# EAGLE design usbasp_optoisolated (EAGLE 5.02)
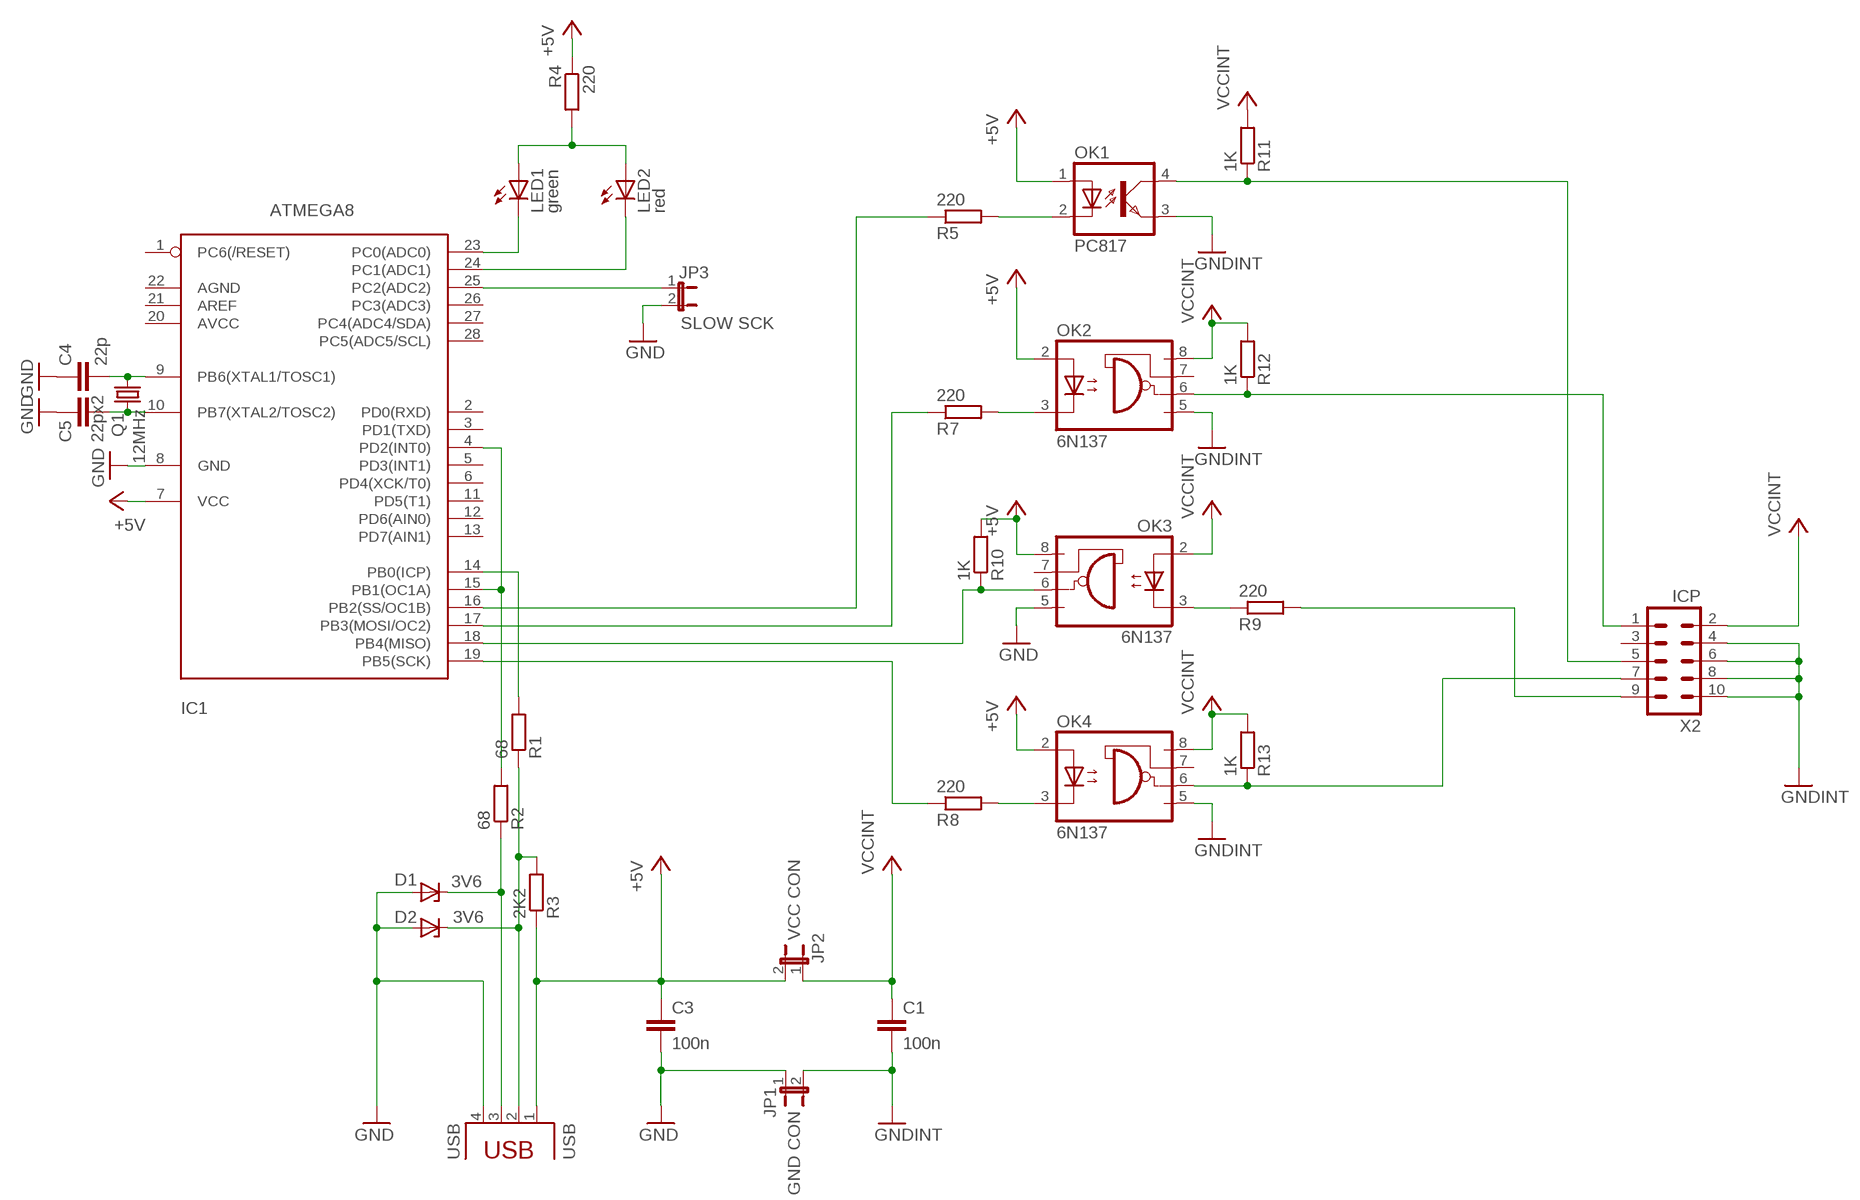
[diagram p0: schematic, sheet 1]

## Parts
C1  100n  C-EU050-024X044  [C050-024X044]
C3  100n  C-EU050-024X044  [C050-024X044]
C4  22p  C-EU025-024X044  [C025-024X044]
C5  22px2  C-EU025-024X044  [C025-024X044]
D1  3V6  ZENER-DIODEDO34-7  [DO34Z7]
D2  3V6  ZENER-DIODEDO34-7  [DO34Z7]
IC1  ATMEGA8  MEGA8-P  [DIL28-3]
JP1  GND CON  JP1E  [JP1]
JP2  VCC CON  JP1E  [JP1]
JP3  SLOW SCK  JP1E  [JP1]
LED1  green  LED3MM  [LED3MM]
LED2  red  LED3MM  [LED3MM]
OK1  PC817  [DIL04]
OK2  6N137  [DIL08]
OK3  6N137  [DIL08]
OK4  6N137  [DIL08]
Q1  12MHz  CRYTALHC49S  [HC49/S]
R1  68  R-EU_0204/5  [0204/5]
R2  68  R-EU_0204/5  [0204/5]
R3  2K2  R-EU_0204/5  [0204/5]
R4  220  R-EU_0204/5  [0204/5]
R5  220  R-EU_0204/5  [0204/5]
R7  220  R-EU_0204/5  [0204/5]
R8  220  R-EU_0204/5  [0204/5]
R9  220  R-EU_0204/5  [0204/5]
R10  1K  R-EU_0204/5  [0204/5]
R11  1K  R-EU_0204/5  [0204/5]
R12  1K  R-EU_0204/5  [0204/5]
R13  1K  R-EU_0204/5  [0204/5]
USB  USB  PN61729  [PN61729]
X2  ICP  ML10L  [ML10L]

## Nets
+5V: C3.1 IC1.7(VCC) JP2.2 OK1.1(A) OK2.2(A) OK3.8(VCC) OK4.2(A) R3.1 R4.1 R10.2 USB.1
GND: C3.2 C4.1 C5.1 D1.A D2.A IC1.8(GND) JP1.1 JP3.2 OK3.5(GND) USB.4
GNDINT: C1.2 JP1.2 OK1.3(EMIT) OK2.5(GND) OK4.5(GND) X2.4 X2.6 X2.8 X2.10
N$1: IC1.16(PB2(SS/OC1B)) R5.1
N$2: OK1.4(COL) R11.1 X2.5
N$3: IC1.17(PB3(MOSI/OC2)) R7.1
N$4: OK4.6(VO) R13.1 X2.7
N$6: R9.2 X2.9
N$8: D1.C R2.1 USB.3
N$9: OK1.2(C) R5.2
N$10: OK2.3(C) R7.2
N$11: OK2.6(VO) R12.1 X2.1
N$12: IC1.25(PC2(ADC2)) JP3.1
N$13: IC1.24(PC1(ADC1)) LED2.K(C)
N$14: IC1.23(PC0(ADC0)) LED1.K(C)
N$15: LED1.A LED2.A R4.2
N$16: IC1.14(PB0(ICP)) R1.2
N$17: IC1.19(PB5(SCK)) R8.1
N$18: OK4.3(C) R8.2
N$19: IC1.4(PD2(INT0)) IC1.15(PB1(OC1A)) R2.2
N$20: IC1.18(PB4(MISO)) OK3.6(VO) R10.1
N$21: OK3.3(C) R9.1
N$22: C4.2 IC1.9(PB6(XTAL1/TOSC1)) Q1.2
N$23: C5.2 IC1.10(PB7(XTAL2/TOSC2)) Q1.1
N$24: D2.C R1.1 R3.2 USB.2
VCCINT: C1.1 JP2.1 OK2.8(VCC) OK3.2(A) OK4.8(VCC) R11.2 R12.2 R13.2 X2.2
Unconnected: IC1.1(PC6(/RESET)) IC1.2(PD0(RXD)) IC1.3(PD1(TXD)) IC1.5(PD3(INT1)) IC1.6(PD4(XCK/T0)) IC1.11(PD5(T1)) IC1.12(PD6(AIN0)) IC1.13(PD7(AIN1)) IC1.20(AVCC) IC1.21(AREF) IC1.22(AGND) IC1.26(PC3(ADC3)) IC1.27(PC4(ADC4/SDA)) IC1.28(PC5(ADC5/SCL)) OK2.7(VE) OK3.7(VE) OK4.7(VE) X2.3

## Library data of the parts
C1 C3-C5 = rcl:C-EU: CAPACITOR, European symbol
D1 D2 = diode:ZENER-DIODE: Z-Diode
IC1 = atmel:MEGA8-P: MICROCONTROLLER 8 Kbytes FLASH 1 kbytes SRAM 512 bytes EEPROM USART 4-channel 10 bit ADC 2-channel 8 bit ADC Source: avr.lbr
JP1-JP3 = jumper:JP1E: JUMPER
LED1 LED2 = led:LED: LED
OK1 = optocoupler:PC817: SHARP OPTO COUPLER
OK2-OK4 = optocoupler:6N137: MOTOROLA OPTO COUPLER
Q1 = crystal:CRYTAL: CRYSTAL
R1-R5 R7-R13 = rcl:R-EU_: RESISTOR, European symbol
USB = con-berg:PN61729: BERG USB connector
X2 = con-harting-ml:ML10: HARTING

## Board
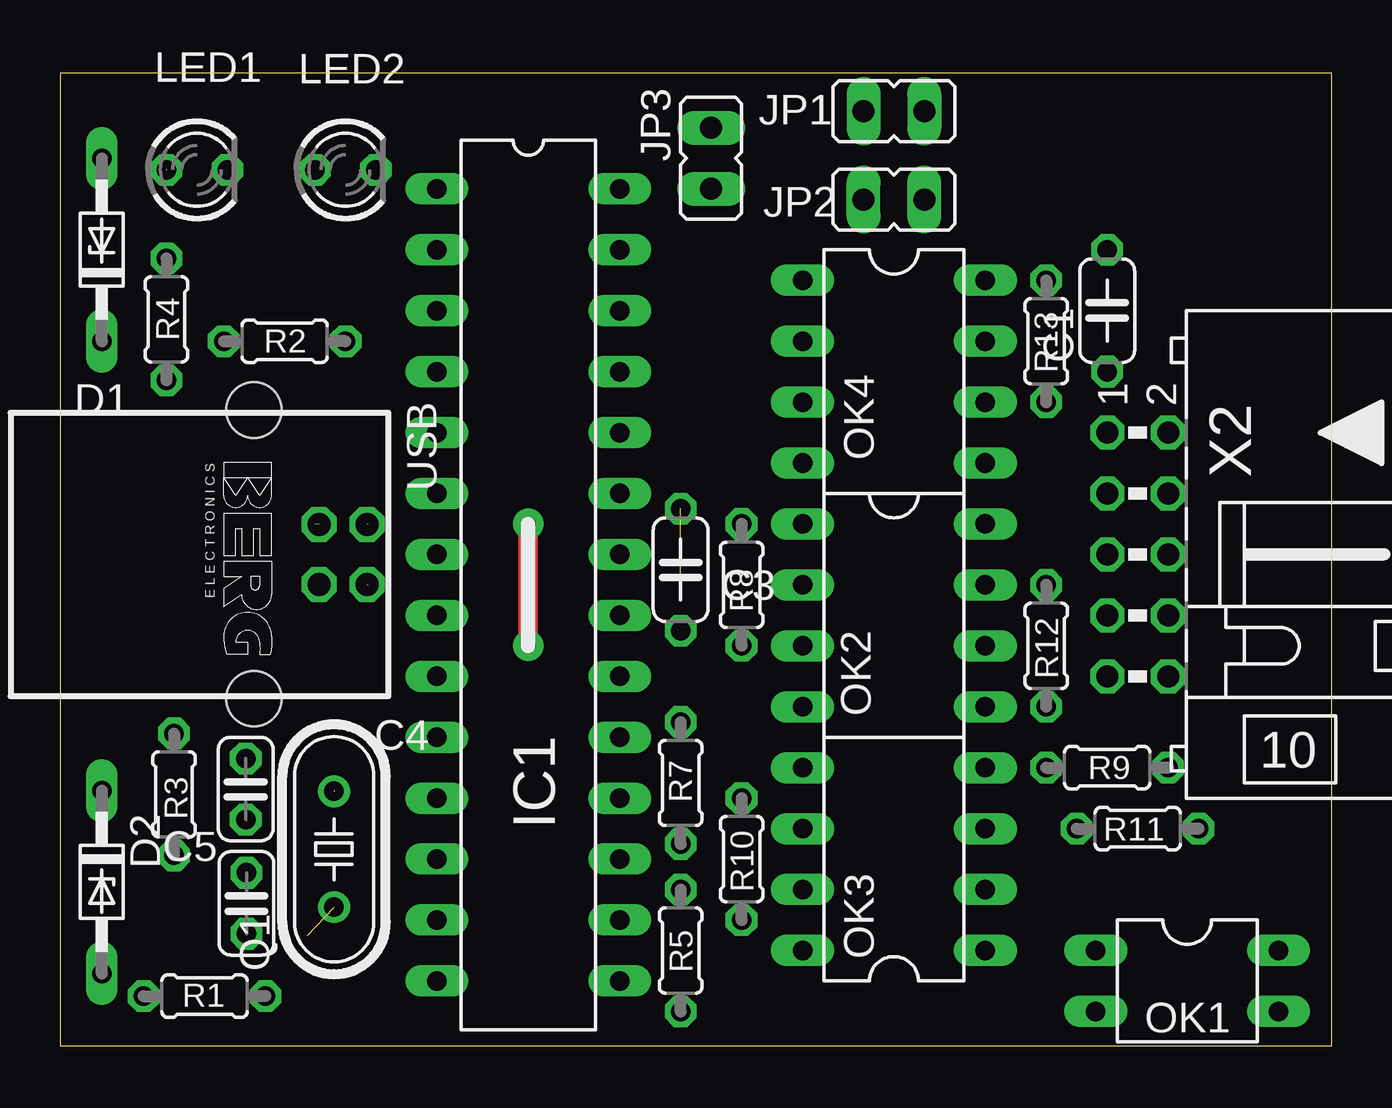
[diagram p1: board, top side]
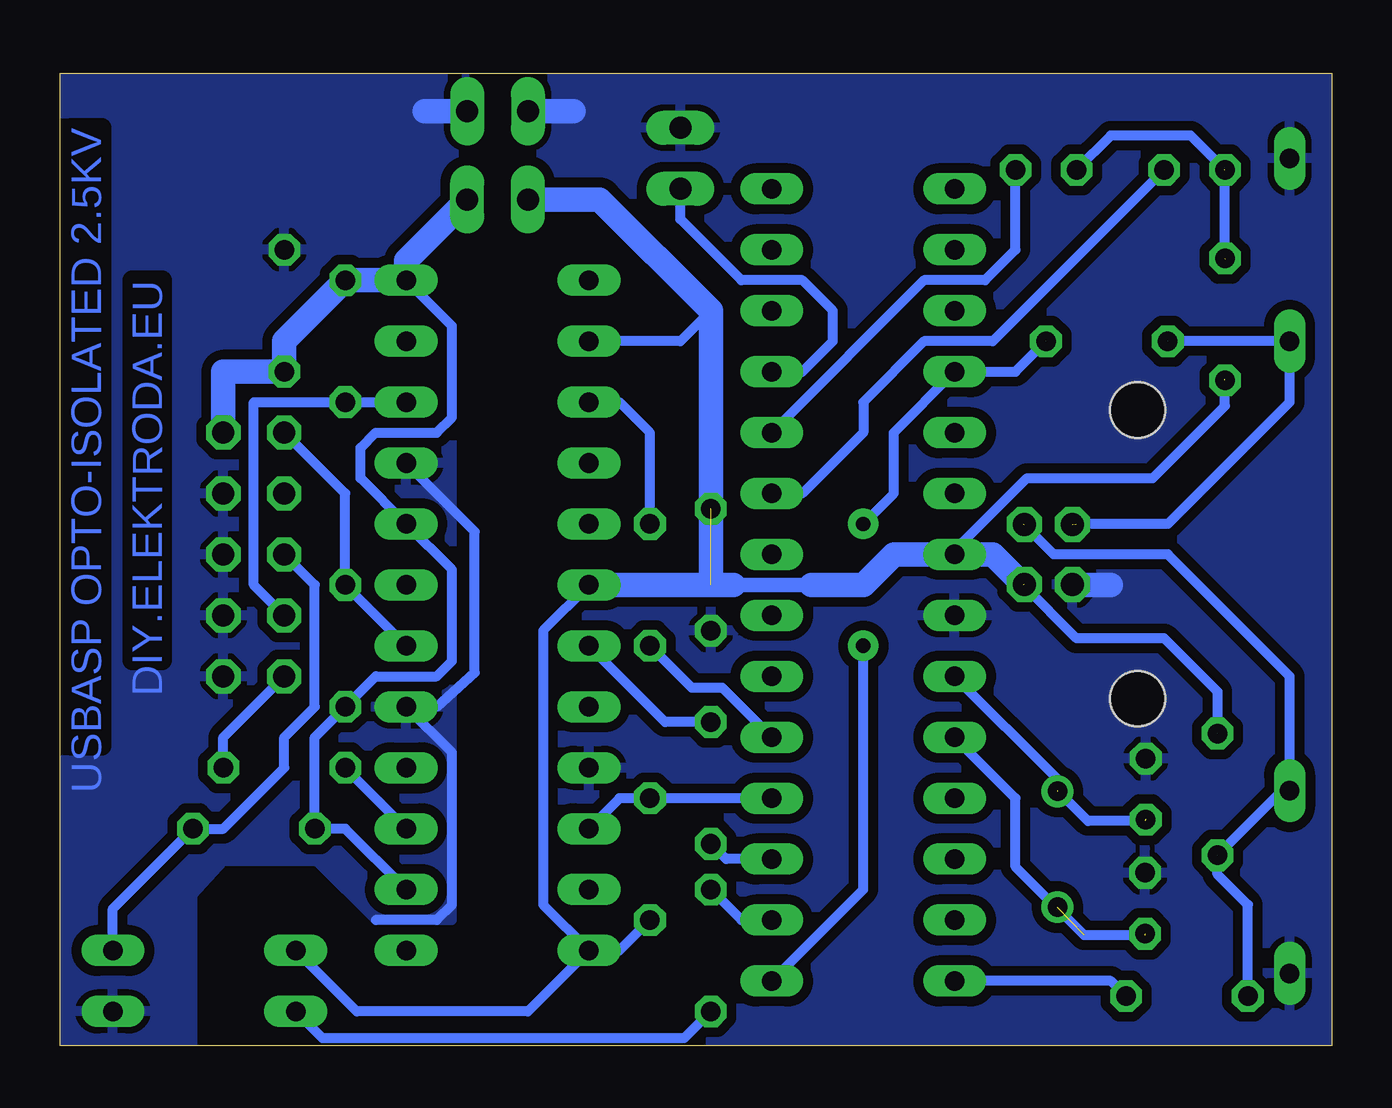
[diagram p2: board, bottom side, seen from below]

Size 53 x 40.52 mm. Coordinates in mm from the lower left corner, seen from the top.
Outline: 0,0 53,0 53,40.52 0,40.52 0,0
Copper layers (1*16): Top 0.035mm / dielectric 1.5mm / Bottom 0.035mm
Design rules "default *": minimum track width 10mil, minimum drill 24mil, track to track 16mil, track to pad 16mil, pad to pad 16mil, via to via 16mil, smd to smd 16mil, copper to edge 1mil, drill to drill 8mil, minimum pad ring 10mil, minimum via ring 8mil, stop-mask expansion 4mil, vias tented up to drill 0mil, thermal gap 10mil

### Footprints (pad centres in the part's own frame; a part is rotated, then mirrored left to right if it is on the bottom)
C050-024X044 = drill 0.813 octagon: 1 -2.54,0; 2 2.54,0
C025-024X044 = drill 0.813 octagon: 1 -1.27,0; 2 1.27,0
DO34Z7 = drill 0.813 long: A 3.81,0; C -3.81,0
DIL28-3 = drill 0.813 long: 1 -16.51,-3.81; 2 -13.97,-3.81; 3 -11.43,-3.81; 4 -8.89,-3.81; 5 -6.35,-3.81; 6 -3.81,-3.81; 7 -1.27,-3.81; 8 1.27,-3.81; 9 3.81,-3.81; 10 6.35,-3.81; 11 8.89,-3.81; 12 11.43,-3.81; 13 13.97,-3.81; 14 16.51,-3.81; 15 16.51,3.81; 16 13.97,3.81; 17 11.43,3.81; 18 8.89,3.81; 19 6.35,3.81; 20 3.81,3.81; 21 1.27,3.81; 22 -1.27,3.81; 23 -3.81,3.81; 24 -6.35,3.81; 25 -8.89,3.81; 26 -11.43,3.81; 27 -13.97,3.81; 28 -16.51,3.81
JP1 = drill 0.914 long: 1 0,-1.27; 2 0,1.27
LED3MM = drill 0.813 octagon: A -1.27,0; K 1.27,0
DIL04 = drill 0.813 long: 1 -1.27,-3.81; 2 1.27,-3.81; 3 1.27,3.81; 4 -1.27,3.81
DIL08 = drill 0.813 long: 1 -3.81,-3.81; 2 -1.27,-3.81; 3 1.27,-3.81; 4 3.81,-3.81; 5 3.81,3.81; 6 1.27,3.81; 7 -1.27,3.81; 8 -3.81,3.81
HC49/S = drill 0.813 round: 1 -2.413,0; 2 2.413,0
0204/5 = drill 0.813 octagon: 1 -2.54,0; 2 2.54,0
PN61729 = drill 0.95 octagon: 1 1.25,4.71; 2 -1.25,4.71; 3 -1.25,2.71; 4 1.25,2.71 | hole 2.3: -6.02,0; 6.02,0
ML10L = drill 0.914 octagon: 1 -5.08,-1.27; 2 -5.08,1.27; 3 -2.54,-1.27; 4 -2.54,1.27; 5 0,-1.27; 6 0,1.27; 7 2.54,-1.27; 8 2.54,1.27; 9 5.08,-1.27; 10 5.08,1.27

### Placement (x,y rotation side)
C1  43.65,30.63 90 top
C3  25.87,19.84 270 top
C4  7.74,10.69 270 top
C5  7.77,5.93 270 top
D1  1.74,33.17 90 top
D2  1.74,6.82 270 top
IC1  19.52,19.2 270 top
JP1  34.76,38.95 270 top
JP2  34.76,35.27 90 top
JP3  27.14,36.98 0 top
LED1  5.71,36.51 0 top
LED2  11.9,36.51 0 top
OK1  46.98,2.69 270 top
OK2  34.76,17.93 270 top
OK3  34.76,7.77 90 top
OK4  34.76,28.09 270 top
Q1  11.42,8.19 90 top
R1  6.03,2.06 0 top
R2  9.36,29.36 0 top
R3  4.76,10.47 270 top
R4  4.44,30.27 90 top
R5  25.87,3.96 270 top
R7  25.87,10.95 90 top
R8  28.41,19.2 90 top
R9  43.65,11.58 0 top
R10  28.41,7.77 270 top
R11  44.92,9.04 180 top
R12  41.11,16.66 270 top
R13  41.11,29.36 90 top
USB  8.09,20.47 270 top
X2  44.92,20.47 270 top

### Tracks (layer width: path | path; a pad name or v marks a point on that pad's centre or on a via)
+5V  (4 unrouted)
  Bottom 0.406: R10.2 29.68,3.96 OK3.8 | OK2.2 32.85,17.3 32.85,5.87 OK3.8 | OK3.8 33.49,1.42 40.63,1.42 OK1.1 | 25.87,30.63 27.14,29.36 OK4.2 | 15.39,20.47 IC1.7 15.71,20.63 12.69,23.65 7.46,23.65 4.44,26.66 4.44,27.78 | 12.85,19.2 10.63,16.98 6.98,16.98 4.76,14.76 R3.1
  Bottom 0.61: 21.68,19.2 24.92,19.2
  Bottom 1.016: 21.68,19.2 19.52,19.2 18.25,20.47 IC1.7 14.12,20.47 12.85,19.2 | 24.92,19.2 25.87,19.2 | 25.87,19.2 OK2.2 | 25.87,19.2 25.87,30.63 30.5,35.27 JP2.2
GND
  Bottom 1.016: 31.58,38.95 33.43,38.95 | 9.2,19.2 10.79,19.2
  pour Bottom: -0.8,40.79 -0.8,-1.12 32.98,-1.18 32.98,40.73
GNDINT
  Bottom 0.406: 39.84,5.23 37.3,5.23 36.66,5.87 36.66,12.22 OK2.5 | 37.3,14.12 35.71,15.55 35.71,21.43 OK4.5
  Bottom 1.016: JP1.2 37.81,38.95
  pour Bottom: 36.09,40.86 53.81,40.79 53.81,-1.12 47.46,-1.12 47.46,6.31 46.19,7.71 42.32,7.71 39.84,5.23 36.66,5.23 36.66,35.65
N$1
  Bottom 0.406: IC1.16 24.6,5.23 R5.1
N$2
  Bottom 0.406: OK1.4 50.79,5.71 R11.1 46.19,9.04 43.65,11.58 43.65,12.85 42.38,14.12 42.38,19.2 X2.5
N$3
  Bottom 0.406: IC1.17 25.23,7.77 R7.1
N$4
  Bottom 0.406: OK4.6 R13.1 44.92,26.82 44.92,19.2 X2.7
N$6
  Bottom 0.406: X2.9 46.19,12.85 R9.2
N$8  (2 unrouted)
  Bottom 0.406: 10.63,21.74 6.82,21.74 1.74,26.82 D1.C R2.1
N$9
  Bottom 0.406: R5.2 26.98,0.31 42.06,0.31 OK1.2
N$10
  Bottom 0.406: OK2.3 27.77,13.49 R7.2
N$11
  Bottom 0.406: OK2.6 R12.1 41.11,23.01 X2.1
N$12
  Bottom 0.406: IC1.25 22.06,28.09 20.79,29.36 20.79,30.63 22.06,31.9 24.6,31.9 27.14,34.44 JP3.1
N$13
  Bottom 0.406: IC1.24 16.98,31.9 14.44,31.9 13.17,33.17 LED2.K
N$14
  Bottom 0.406: IC1.23 22.06,23.01 19.52,25.55 19.52,26.82 16.98,29.36 14.12,29.36 LED1.K
N$15  (2 unrouted)
  Bottom 0.406: LED1.A 5.87,37.94 9.2,37.94 LED2.A | LED1.A 4.45,32.79
N$16
  Bottom 0.406: R1.2 9.2,2.69 IC1.14
N$17
  Bottom 0.406: IC1.19 25.39,14.92 26.66,14.92 R8.1
N$18
  Bottom 0.406: R8.2 28.41,25.55 29.68,26.82 OK4.3
N$19  (via drill 0.6 pad 1.27)  (1 unrouted)
  Top 0: v19.52,16.66 v19.52,21.74
  Top 0.813: v19.52,16.66 v19.52,21.74
  Bottom 0.406: IC1.15 19.52,6.5 v19.52,16.66 | v19.52,21.74 18.25,23.01 18.25,24.28 18.25,25.55 IC1.4 13.17,28.09 R2.2
N$20
  Bottom 0.406: IC1.18 R10.1 29.68,10.31 OK3.6
N$21
  Bottom 0.406: OK3.3 R9.1
N$22  (2 unrouted)
  Bottom 0.406: IC1.9 11.42,11.11 11.42,10.63 10.15,9.36 7.77,9.36
N$23  (2 unrouted)
  Bottom 0.406: IC1.10 13.17,10.31 13.17,7.46 10.31,4.6 7.77,4.6
N$24  (2 unrouted)
  Bottom 0.406: 12.85,21.74 11.58,20.47 6.82,20.47 1.74,15.39 D2.C 2.06,10.63 2.22,10.47 R3.2 4.76,7.14 3.49,5.87 R1.1
VCCINT
  Bottom 0.406: OK3.2 41.11,9.04 R11.2 42.38,12.85 R12.2 39.84,15.39 37.3,15.39 36.66,16.03 36.66,19.84 OK2.8 40.48,23.65 40.48,24.92 39.84,25.55 37.3,25.55 36.66,26.19 36.66,30 OK4.8 R13.2
  Bottom 1.016: JP2.1 38.57,32.73 OK4.8 R13.2 43.65,29.36 C1.1 46.19,28.09 X2.2

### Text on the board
Bottom: USBASP OPTO-ISOLATED 2.5KV | DIY.ELEKTRODA.EU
